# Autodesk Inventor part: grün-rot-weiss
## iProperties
Created: 2004-10
Part Number: grün-rot-weiss
Document SubType Name: Modeling
Designer: sahrens
Manufacturer: Standard
Standards Organization: Custom
Author: sahrens
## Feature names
1. Extrusion1
2. Rundung2 [Fillet]
